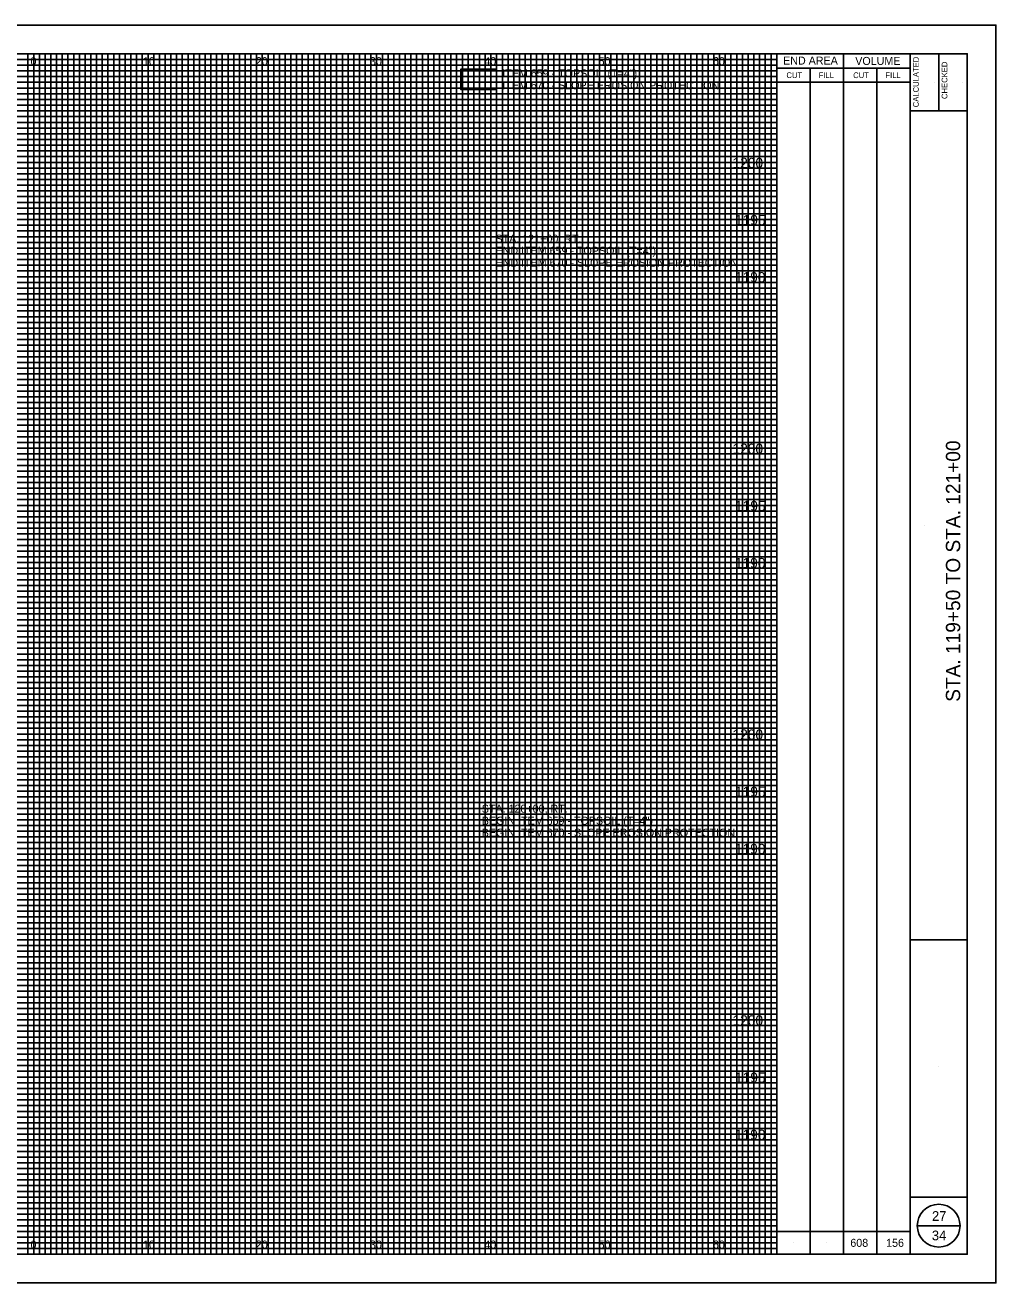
# Model space of a CAD drawing. Extents: x -10 to 160, y -13 to 1488.
# Drawn here: x 75.1 to 160, y 1147.5 to 1257.5 of the extents above; entities that cross this region are included whole.
import ezdxf

# ---------------------------------------------------------------- set-up
doc = ezdxf.new("R2010")
doc.units = 0
for name, color, linetype in [('DR_X_Storm_Sewer', 7, 'Continuous'), ('GK_Cells', 7, 'Continuous'), ('PF_P_Sta_Elev_Text', 7, 'Continuous'), ('PF_X_Ground_Line', 7, 'Continuous'), ('PV_P_EOP', 7, 'Continuous'), ('PV_P_Saw_Cut_Line', 7, 'Continuous'), ('PV_P_Shoulder', 7, 'Continuous'), ('XS_P_Pavt_Layers', 7, 'Continuous')]:
    doc.layers.add(name, color=color, linetype=linetype)

msp = doc.modelspace()

# ---------------------------------------------------------------- linework, layer by layer
at = {"layer": 'GK_Cells'}
for p, q in [((152.5, 1150), (152.5, 1255)), ((155, 1255), (155, 1250)), ((152.5, 1250), (157.5, 1250)), ((152.5, 1177.5), (157.5, 1177.5)), ((152.5, 1155), (157.5, 1155))]:
    msp.add_line(p, q, dxfattribs=at)
msp.add_lwpolyline([(0, 1255), (157.5, 1255), (157.5, 1150), (0, 1150)], close=True, dxfattribs=at)
at = {"layer": 'PF_P_Sta_Elev_Text'}
msp.add_lwpolyline([(-10, 1147.5), (160, 1147.5), (160, 1257.5), (-10, 1257.5)], close=True, dxfattribs=at)
at = {"layer": 'PF_X_Ground_Line'}
for p, q in [((140.83, 1150), (140.83, 1255)), ((146.67, 1150), (146.67, 1255)), ((140.83, 1253.75), (152.5, 1253.75)), ((143.75, 1150), (143.75, 1253.75)), ((149.58, 1150), (149.58, 1253.75)), ((140.83, 1252.5), (152.5, 1252.5)), ((154.6, 1252.52), (154.6, 1252.52)), ((157.1, 1252.52), (157.1, 1252.52)), ((153.75, 1213.75), (153.75, 1213.75)), ((156.26, 1213.75), (156.26, 1213.75)), ((155, 1166.46), (155, 1166.46)), ((155, 1152.92), (155, 1152.92)), ((140.83, 1152), (152.5, 1152)), ((153.12, 1152.5), (156.88, 1152.5)), ((142.29, 1151), (142.29, 1151)), ((145.21, 1151), (145.21, 1151)), ((148.12, 1151), (148.12, 1151)), ((151.04, 1151), (151.04, 1151)), ((155, 1151.22), (155, 1151.22))]:
    msp.add_line(p, q, dxfattribs=at)
msp.add_circle((155, 1152.5), 1.87, dxfattribs=at)
at = {"layer": 'PV_P_EOP'}
for p, q in [((5.83, 1254.5), (140.83, 1254.5)), ((5.83, 1254), (140.83, 1254)), ((75.33, 1150), (75.33, 1255)), ((76.33, 1150), (76.33, 1255)), ((76.83, 1150), (76.83, 1255)), ((77.33, 1150), (77.33, 1255)), ((77.83, 1150), (77.83, 1255)), ((78.33, 1150), (78.33, 1255)), ((78.83, 1150), (78.83, 1255)), ((79.33, 1150), (79.33, 1255)), ((79.83, 1150), (79.83, 1255)), ((80.33, 1150), (80.33, 1255)), ((81.33, 1150), (81.33, 1255)), ((81.83, 1150), (81.83, 1255)), ((82.33, 1150), (82.33, 1255)), ((82.83, 1150), (82.83, 1255)), ((83.33, 1150), (83.33, 1255)), ((83.83, 1150), (83.83, 1255)), ((84.33, 1150), (84.33, 1255)), ((84.83, 1150), (84.83, 1255)), ((85.33, 1150), (85.33, 1255)), ((86.33, 1150), (86.33, 1255)), ((86.83, 1150), (86.83, 1255)), ((87.33, 1150), (87.33, 1255)), ((87.83, 1150), (87.83, 1255)), ((88.33, 1150), (88.33, 1255)), ((88.83, 1150), (88.83, 1255)), ((89.33, 1150), (89.33, 1255)), ((89.83, 1150), (89.83, 1255)), ((90.33, 1150), (90.33, 1255)), ((91.33, 1150), (91.33, 1255)), ((91.83, 1150), (91.83, 1255)), ((92.33, 1150), (92.33, 1255)), ((92.83, 1150), (92.83, 1255)), ((93.33, 1150), (93.33, 1255)), ((93.83, 1150), (93.83, 1255)), ((94.33, 1150), (94.33, 1255)), ((94.83, 1150), (94.83, 1255)), ((95.33, 1150), (95.33, 1255)), ((96.33, 1150), (96.33, 1255)), ((96.83, 1150), (96.83, 1255)), ((97.33, 1150), (97.33, 1255)), ((97.83, 1150), (97.83, 1255)), ((98.33, 1150), (98.33, 1255)), ((98.83, 1150), (98.83, 1255)), ((99.33, 1150), (99.33, 1255)), ((99.83, 1150), (99.83, 1255)), ((100.33, 1150), (100.33, 1255)), ((101.33, 1150), (101.33, 1255)), ((101.83, 1150), (101.83, 1255)), ((102.33, 1150), (102.33, 1255)), ((102.83, 1150), (102.83, 1255)), ((103.33, 1150), (103.33, 1255)), ((103.83, 1150), (103.83, 1255)), ((104.33, 1150), (104.33, 1255)), ((104.83, 1150), (104.83, 1255)), ((105.33, 1150), (105.33, 1255)), ((106.33, 1150), (106.33, 1255)), ((106.83, 1150), (106.83, 1255)), ((107.33, 1150), (107.33, 1255)), ((107.83, 1150), (107.83, 1255)), ((108.33, 1150), (108.33, 1255)), ((108.83, 1150), (108.83, 1255)), ((109.33, 1150), (109.33, 1255)), ((109.83, 1150), (109.83, 1255)), ((110.33, 1150), (110.33, 1255)), ((111.33, 1150), (111.33, 1255)), ((111.83, 1150), (111.83, 1255)), ((112.33, 1150), (112.33, 1255)), ((112.83, 1150), (112.83, 1255)), ((113.33, 1150), (113.33, 1255)), ((113.83, 1150), (113.83, 1255)), ((114.33, 1150), (114.33, 1255)), ((114.83, 1150), (114.83, 1255)), ((115.33, 1150), (115.33, 1255)), ((116.33, 1150), (116.33, 1255)), ((116.83, 1150), (116.83, 1255)), ((117.33, 1150), (117.33, 1255)), ((117.83, 1150), (117.83, 1255)), ((118.33, 1150), (118.33, 1255)), ((118.83, 1150), (118.83, 1255)), ((119.33, 1150), (119.33, 1255)), ((119.83, 1150), (119.83, 1255)), ((120.33, 1150), (120.33, 1255)), ((121.33, 1150), (121.33, 1255)), ((121.83, 1150), (121.83, 1255)), ((122.33, 1150), (122.33, 1255)), ((122.83, 1150), (122.83, 1255)), ((123.33, 1150), (123.33, 1255)), ((123.83, 1150), (123.83, 1255)), ((124.33, 1150), (124.33, 1255)), ((124.83, 1150), (124.83, 1255)), ((125.33, 1150), (125.33, 1255)), ((126.33, 1150), (126.33, 1255)), ((126.83, 1150), (126.83, 1255)), ((127.33, 1150), (127.33, 1255)), ((127.83, 1150), (127.83, 1255)), ((128.33, 1150), (128.33, 1255)), ((128.83, 1150), (128.83, 1255)), ((129.33, 1150), (129.33, 1255)), ((129.83, 1150), (129.83, 1255)), ((130.33, 1150), (130.33, 1255)), ((131.33, 1150), (131.33, 1255)), ((131.83, 1150), (131.83, 1255)), ((132.33, 1150), (132.33, 1255)), ((132.83, 1150), (132.83, 1255)), ((133.33, 1150), (133.33, 1255)), ((133.83, 1150), (133.83, 1255)), ((134.33, 1150), (134.33, 1255)), ((134.83, 1150), (134.83, 1255)), ((135.33, 1150), (135.33, 1255)), ((136.33, 1150), (136.33, 1255)), ((136.83, 1150), (136.83, 1255)), ((137.33, 1150), (137.33, 1255)), ((137.83, 1150), (137.83, 1255)), ((138.33, 1150), (138.33, 1255)), ((138.83, 1150), (138.83, 1255)), ((139.33, 1150), (139.33, 1255)), ((139.83, 1150), (139.83, 1255)), ((140.33, 1150), (140.33, 1255)), ((5.83, 1253.5), (140.83, 1253.5)), ((5.83, 1253), (140.83, 1253)), ((5.83, 1252.5), (140.83, 1252.5)), ((5.83, 1252), (140.83, 1252)), ((5.83, 1251.5), (140.83, 1251.5)), ((5.83, 1251), (140.83, 1251)), ((5.83, 1250.5), (140.83, 1250.5)), ((5.83, 1249.5), (140.83, 1249.5)), ((5.83, 1249), (140.83, 1249)), ((5.83, 1248.5), (140.83, 1248.5)), ((5.83, 1248), (140.83, 1248)), ((5.83, 1247.5), (140.83, 1247.5)), ((5.83, 1247), (140.83, 1247)), ((5.83, 1246.5), (140.83, 1246.5)), ((5.83, 1246), (140.83, 1246)), ((5.83, 1245.5), (140.83, 1245.5)), ((5.83, 1244.5), (140.83, 1244.5)), ((5.83, 1244), (140.83, 1244)), ((5.83, 1243.5), (140.83, 1243.5)), ((5.83, 1243), (140.83, 1243)), ((5.83, 1242.5), (140.83, 1242.5)), ((5.83, 1242), (140.83, 1242)), ((5.83, 1241.5), (140.83, 1241.5)), ((5.83, 1241), (140.83, 1241)), ((5.83, 1240.5), (140.83, 1240.5)), ((5.83, 1239.5), (140.83, 1239.5)), ((5.83, 1239), (140.83, 1239)), ((5.83, 1238.5), (140.83, 1238.5)), ((5.83, 1238), (140.83, 1238)), ((5.83, 1237.5), (140.83, 1237.5)), ((5.83, 1237), (140.83, 1237)), ((5.83, 1236.5), (140.83, 1236.5)), ((5.83, 1236), (140.83, 1236)), ((5.83, 1235.5), (140.83, 1235.5)), ((5.83, 1234.5), (140.83, 1234.5)), ((5.83, 1234), (140.83, 1234)), ((5.83, 1233.5), (140.83, 1233.5)), ((5.83, 1233), (140.83, 1233)), ((5.83, 1232.5), (140.83, 1232.5)), ((5.83, 1232), (140.83, 1232)), ((5.83, 1231.5), (140.83, 1231.5)), ((5.83, 1231), (140.83, 1231)), ((5.83, 1230.5), (140.83, 1230.5)), ((5.83, 1229.5), (140.83, 1229.5)), ((5.83, 1229), (140.83, 1229)), ((5.83, 1228.5), (140.83, 1228.5)), ((5.83, 1228), (140.83, 1228)), ((5.83, 1227.5), (140.83, 1227.5)), ((5.83, 1227), (140.83, 1227)), ((5.83, 1226.5), (140.83, 1226.5)), ((5.83, 1226), (140.83, 1226)), ((5.83, 1225.5), (140.83, 1225.5)), ((5.83, 1224.5), (140.83, 1224.5)), ((5.83, 1224), (140.83, 1224)), ((5.83, 1223.5), (140.83, 1223.5)), ((5.83, 1223), (140.83, 1223)), ((5.83, 1222.5), (140.83, 1222.5)), ((5.83, 1222), (140.83, 1222)), ((5.83, 1221.5), (140.83, 1221.5)), ((5.83, 1221), (140.83, 1221)), ((5.83, 1220.5), (140.83, 1220.5)), ((5.83, 1219.5), (140.83, 1219.5)), ((5.83, 1219), (140.83, 1219)), ((5.83, 1218.5), (140.83, 1218.5)), ((5.83, 1218), (140.83, 1218)), ((5.83, 1217.5), (140.83, 1217.5)), ((5.83, 1217), (140.83, 1217)), ((5.83, 1216.5), (140.83, 1216.5)), ((5.83, 1216), (140.83, 1216)), ((5.83, 1215.5), (140.83, 1215.5)), ((5.83, 1214.5), (140.83, 1214.5)), ((5.83, 1214), (140.83, 1214)), ((5.83, 1213.5), (140.83, 1213.5)), ((5.83, 1213), (140.83, 1213)), ((5.83, 1212.5), (140.83, 1212.5)), ((5.83, 1212), (140.83, 1212)), ((5.83, 1211.5), (140.83, 1211.5)), ((5.83, 1211), (140.83, 1211)), ((5.83, 1210.5), (140.83, 1210.5)), ((5.83, 1209.5), (140.83, 1209.5)), ((5.83, 1209), (140.83, 1209)), ((5.83, 1208.5), (140.83, 1208.5)), ((5.83, 1208), (140.83, 1208)), ((5.83, 1207.5), (140.83, 1207.5)), ((5.83, 1207), (140.83, 1207)), ((5.83, 1206.5), (140.83, 1206.5)), ((5.83, 1206), (140.83, 1206)), ((5.83, 1205.5), (140.83, 1205.5)), ((5.83, 1204.5), (140.83, 1204.5)), ((5.83, 1204), (140.83, 1204)), ((5.83, 1203.5), (140.83, 1203.5)), ((5.83, 1203), (140.83, 1203)), ((5.83, 1202.5), (140.83, 1202.5)), ((5.83, 1202), (140.83, 1202)), ((5.83, 1201.5), (140.83, 1201.5)), ((5.83, 1201), (140.83, 1201)), ((5.83, 1200.5), (140.83, 1200.5)), ((5.83, 1199.5), (140.83, 1199.5)), ((5.83, 1199), (140.83, 1199)), ((5.83, 1198.5), (140.83, 1198.5)), ((5.83, 1198), (140.83, 1198)), ((5.83, 1197.5), (140.83, 1197.5)), ((5.83, 1197), (140.83, 1197)), ((5.83, 1196.5), (140.83, 1196.5)), ((5.83, 1196), (140.83, 1196)), ((5.83, 1195.5), (140.83, 1195.5)), ((5.83, 1194.5), (140.83, 1194.5)), ((5.83, 1194), (140.83, 1194)), ((5.83, 1193.5), (140.83, 1193.5)), ((5.83, 1193), (140.83, 1193)), ((5.83, 1192.5), (140.83, 1192.5)), ((5.83, 1192), (140.83, 1192)), ((5.83, 1191.5), (140.83, 1191.5)), ((5.83, 1191), (140.83, 1191)), ((5.83, 1190.5), (140.83, 1190.5)), ((5.83, 1189.5), (140.83, 1189.5)), ((5.83, 1189), (140.83, 1189)), ((5.83, 1188.5), (140.83, 1188.5)), ((5.83, 1188), (140.83, 1188)), ((5.83, 1187.5), (140.83, 1187.5)), ((5.83, 1187), (140.83, 1187)), ((5.83, 1186.5), (140.83, 1186.5)), ((5.83, 1186), (140.83, 1186)), ((5.83, 1185.5), (140.83, 1185.5)), ((5.83, 1184.5), (140.83, 1184.5)), ((5.83, 1184), (140.83, 1184)), ((5.83, 1183.5), (140.83, 1183.5)), ((5.83, 1183), (140.83, 1183)), ((5.83, 1182.5), (140.83, 1182.5)), ((5.83, 1182), (140.83, 1182)), ((5.83, 1181.5), (140.83, 1181.5)), ((5.83, 1181), (140.83, 1181)), ((5.83, 1180.5), (140.83, 1180.5)), ((5.83, 1179.5), (140.83, 1179.5)), ((5.83, 1179), (140.83, 1179)), ((5.83, 1178.5), (140.83, 1178.5)), ((5.83, 1178), (140.83, 1178)), ((5.83, 1177.5), (140.83, 1177.5)), ((5.83, 1177), (140.83, 1177)), ((5.83, 1176.5), (140.83, 1176.5)), ((5.83, 1176), (140.83, 1176)), ((5.83, 1175.5), (140.83, 1175.5)), ((5.83, 1174.5), (140.83, 1174.5)), ((5.83, 1174), (140.83, 1174)), ((5.83, 1173.5), (140.83, 1173.5)), ((5.83, 1173), (140.83, 1173)), ((5.83, 1172.5), (140.83, 1172.5)), ((5.83, 1172), (140.83, 1172)), ((5.83, 1171.5), (140.83, 1171.5)), ((5.83, 1171), (140.83, 1171)), ((5.83, 1170.5), (140.83, 1170.5)), ((5.83, 1169.5), (140.83, 1169.5)), ((5.83, 1169), (140.83, 1169)), ((5.83, 1168.5), (140.83, 1168.5)), ((5.83, 1168), (140.83, 1168)), ((5.83, 1167.5), (140.83, 1167.5)), ((5.83, 1167), (140.83, 1167)), ((5.83, 1166.5), (140.83, 1166.5)), ((5.83, 1166), (140.83, 1166)), ((5.83, 1165.5), (140.83, 1165.5)), ((5.83, 1164.5), (140.83, 1164.5)), ((5.83, 1164), (140.83, 1164)), ((5.83, 1163.5), (140.83, 1163.5)), ((5.83, 1163), (140.83, 1163)), ((5.83, 1162.5), (140.83, 1162.5)), ((5.83, 1162), (140.83, 1162)), ((5.83, 1161.5), (140.83, 1161.5)), ((5.83, 1161), (140.83, 1161)), ((5.83, 1160.5), (140.83, 1160.5)), ((5.83, 1159.5), (140.83, 1159.5)), ((5.83, 1159), (140.83, 1159)), ((5.83, 1158.5), (140.83, 1158.5)), ((5.83, 1158), (140.83, 1158)), ((5.83, 1157.5), (140.83, 1157.5)), ((5.83, 1157), (140.83, 1157)), ((5.83, 1156.5), (140.83, 1156.5)), ((5.83, 1156), (140.83, 1156)), ((5.83, 1155.5), (140.83, 1155.5)), ((5.83, 1154.5), (140.83, 1154.5)), ((5.83, 1154), (140.83, 1154)), ((5.83, 1153.5), (140.83, 1153.5)), ((5.83, 1153), (140.83, 1153)), ((5.83, 1152.5), (140.83, 1152.5)), ((5.83, 1152), (140.83, 1152)), ((5.83, 1151.5), (140.83, 1151.5)), ((5.83, 1151), (140.83, 1151)), ((5.83, 1150.5), (140.83, 1150.5))]:
    msp.add_line(p, q, dxfattribs=at)
at = {"layer": 'PV_P_Saw_Cut_Line'}
msp.add_lwpolyline([(113.21, 1253.66), (116.32, 1253.66), (116.32, 1251.87), (113.21, 1251.87)], close=True, dxfattribs=at)
msp.add_lwpolyline([(113.21, 1251.87), (116.32, 1251.87), (116.32, 1253.66), (113.21, 1253.66), (113.21, 1251.87)], dxfattribs=at)
at = {"layer": 'PV_P_Shoulder'}
for p, q in [((75.83, 1150), (75.83, 1255)), ((80.83, 1150), (80.83, 1255)), ((85.83, 1150), (85.83, 1255)), ((90.83, 1150), (90.83, 1255)), ((95.83, 1150), (95.83, 1255)), ((100.83, 1150), (100.83, 1255)), ((105.83, 1150), (105.83, 1255)), ((110.83, 1150), (110.83, 1255)), ((115.83, 1150), (115.83, 1255)), ((120.83, 1150), (120.83, 1255)), ((125.83, 1150), (125.83, 1255)), ((130.83, 1150), (130.83, 1255)), ((135.83, 1150), (135.83, 1255)), ((11.66, 1250), (140.83, 1250)), ((11.66, 1245), (140.83, 1245)), ((11.66, 1240), (140.83, 1240)), ((11.66, 1235), (140.83, 1235)), ((11.66, 1230), (140.83, 1230)), ((11.66, 1225), (140.83, 1225)), ((11.66, 1220), (140.83, 1220)), ((11.66, 1215), (140.83, 1215)), ((11.66, 1210), (140.83, 1210)), ((11.66, 1205), (140.83, 1205)), ((11.66, 1200), (140.83, 1200)), ((11.66, 1195), (140.83, 1195)), ((11.66, 1190), (140.83, 1190)), ((11.66, 1185), (140.83, 1185)), ((11.66, 1180), (140.83, 1180)), ((11.66, 1175), (140.83, 1175)), ((11.66, 1170), (140.83, 1170)), ((11.66, 1165), (140.83, 1165)), ((11.66, 1160), (140.83, 1160)), ((11.66, 1155), (140.83, 1155))]:
    msp.add_line(p, q, dxfattribs=at)

# ---------------------------------------------------------------- texts
at = {"layer": 'DR_X_Storm_Sewer'}
for s, height, p in [('0', 0.7, (75.55, 1254)), ('0', 0.7, (75.55, 1254)), ('10', 0.7, (85.39, 1254)), ('20', 0.7, (95.26, 1254)), ('30', 0.7, (105.25, 1254)), ('40', 0.7, (115.25, 1254)), ('50', 0.7, (125.25, 1254)), ('60', 0.7, (135.25, 1254)), ('1200', 0.9, (136.96, 1245)), ('1195', 0.9, (137.18, 1240)), ('1190', 0.9, (137.17, 1235)), ('1200', 0.9, (136.96, 1220)), ('1195', 0.9, (137.18, 1215)), ('1190', 0.9, (137.17, 1210)), ('1200', 0.9, (136.96, 1195)), ('1195', 0.9, (137.18, 1190)), ('1190', 0.9, (137.17, 1185)), ('1200', 0.9, (136.96, 1170)), ('1195', 0.9, (137.18, 1165)), ('1190', 0.9, (137.17, 1160)), ('27', 0.85, (154.41, 1152.92)), ('34', 0.85, (154.4, 1151.22)), ('0', 0.7, (75.55, 1150.5)), ('0', 0.7, (75.55, 1150.5)), ('10', 0.7, (85.39, 1150.5)), ('20', 0.7, (95.26, 1150.5)), ('30', 0.7, (105.25, 1150.5)), ('40', 0.7, (115.25, 1150.5)), ('50', 0.7, (125.25, 1150.5)), ('60', 0.7, (135.25, 1150.5)), ('608', 0.7, (147.27, 1150.65)), ('156', 0.7, (150.4, 1150.65))]:
    msp.add_text(s, height=height, dxfattribs=at).set_placement(p)
at = {"layer": 'PF_X_Ground_Line'}
for s, height, p in [('END AREA', 0.7, (141.39, 1254.05)), ('VOLUME', 0.7, (147.7, 1254.02)), ('CUT', 0.5, (141.68, 1252.87)), ('FILL', 0.5, (144.5, 1252.87)), ('CUT', 0.5, (147.52, 1252.87)), ('FILL', 0.5, (150.34, 1252.87))]:
    msp.add_text(s, height=height, dxfattribs=at).set_placement(p)
for s, height, p in [('CALCULATED', 0.5, (153.26, 1250.32)), ('CHECKED', 0.5, (155.76, 1251.04)), ('STA. 119+50 TO STA. 121+00', 1.25, (156.88, 1198.32))]:
    msp.add_text(s, height=height, rotation=90, dxfattribs=at).set_placement(p)
at = {"layer": 'XS_P_Pavt_Layers'}
for s, p in [('ITEM 659 - TOPSOIL (T=4")', (116.82, 1252.94)), ('ITEM 670 - SLOPE EROSION PROTECTION', (116.82, 1251.89)), ('STA. 121+00, RT.', (116.23, 1238.47)), ('END ITEM 659 - TOPSOIL (T=4")', (116.23, 1237.42)), ('END ITEM 670 - SLOPE EROSION PROTECTION', (116.23, 1236.37)), ('STA. 120+00, RT.', (115.03, 1188.62)), ('BEGIN ITEM 659 - TOPSOIL (T=4")', (115.03, 1187.57)), ('BEGIN ITEM 670 - SLOPE EROSION PROTECTION', (115.03, 1186.52))]:
    msp.add_text(s, height=0.7, dxfattribs=at).set_placement(p)

doc.saveas('drawing.dxf')
